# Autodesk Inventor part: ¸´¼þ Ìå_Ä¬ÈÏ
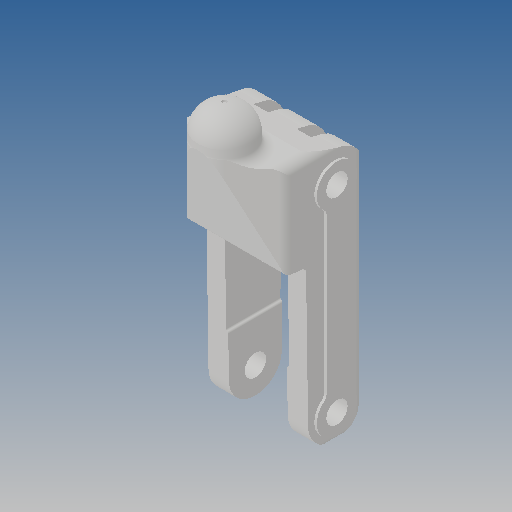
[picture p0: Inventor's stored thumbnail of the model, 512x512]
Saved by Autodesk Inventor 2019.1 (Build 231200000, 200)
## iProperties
Created: 2012-10
Part Number: ¸´¼þ Ìå_Ä¬ÈÏ
Material: Ogólny
Document SubType Name: Modeling
Designer: CADENGINEERING4
Density: 1 g/cm^3
Appearance: Domyślna
Author: CADENGINEERING4
Revision Number: ÈÎºÎ
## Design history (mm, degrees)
feature "NONE"
node "Bryła1"
